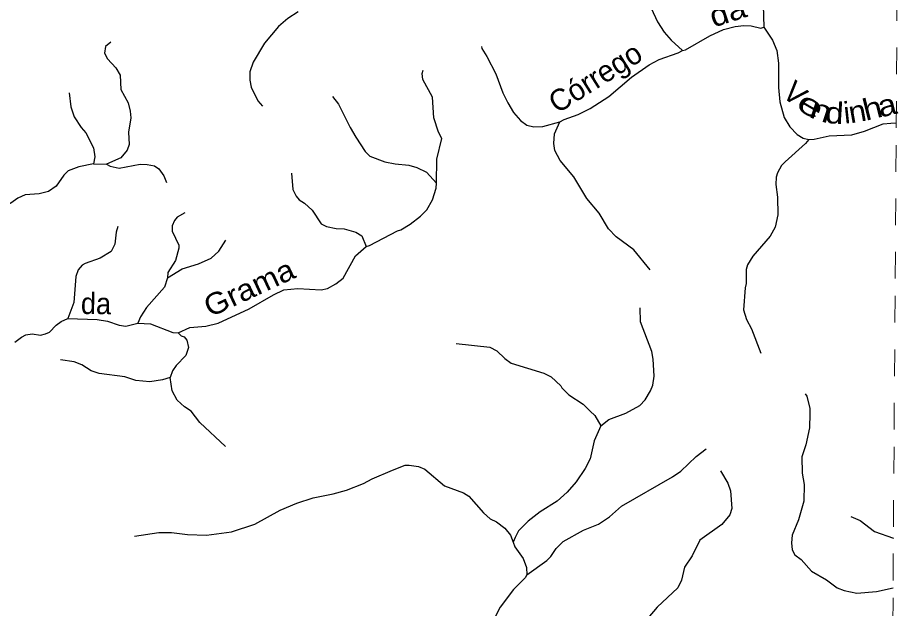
# Model space of a CAD drawing. Extents: x 577 to 602.9, y 7483.8 to 7511.6.
# Drawn here: x 599.47 to 602.787, y 7493.838 to 7496.049 of the extents above; entities that cross this region are included whole.
import ezdxf
from ezdxf.enums import TextEntityAlignment as Align

# ---------------------------------------------------------------- set-up
doc = ezdxf.new("R2010")
doc.units = 0
doc.header["$LTSCALE"] = 0.032
doc.linetypes.add('SHORT_DASHED', pattern=[2.7, 1.5, -1.2])
doc.layers.add('53', color=7, linetype='SHORT_DASHED', lineweight=13)
doc.layers.add('7', color=7, linetype='Continuous', lineweight=25)
doc.layers.add('61', color=7, linetype='Continuous')

msp = doc.modelspace()

# ---------------------------------------------------------------- linework, layer by layer
at = {"layer": '53'}
msp.add_lwpolyline([(602.7419, 7493.3777), (602.7457, 7493.9426), (602.7495, 7494.5074), (602.7533, 7495.0722), (602.7571, 7495.6371), (602.7609, 7496.2019), (602.7646, 7496.7668), (602.7684, 7497.3316), (602.7722, 7497.8964), (602.776, 7498.4613), (602.7798, 7499.0261), (602.7836, 7499.5909), (602.7874, 7500.1558)], dxfattribs=at)
at = {"layer": '7'}
for points in [[(601.7732, 7496.2353), (601.7792, 7496.1875), (601.8004, 7496.1368), (601.8405, 7496.0853), (601.8634, 7496.0338), (601.8887, 7495.9954), (601.9148, 7495.9652), (601.9574, 7495.9268)], [(602.3236, 7496.2227), (602.308, 7496.1949), (602.3015, 7496.1671), (602.2729, 7496.1295), (602.259, 7496.096), (602.2614, 7496.0134)], [(600.5195, 7496.0706), (600.4803, 7496.0461), (600.446, 7496.0159), (600.3937, 7495.9537), (600.3503, 7495.8826), (600.3389, 7495.8458), (600.3389, 7495.8148), (600.3438, 7495.7886), (600.3683, 7495.7379), (600.3851, 7495.718)], [(601.9574, 7495.9268), (601.9688, 7495.9284), (602.0595, 7495.9807), (602.111, 7496.0044), (602.1543, 7496.0159), (602.187, 7496.0199), (602.2148, 7496.0191), (602.25, 7496.0101), (602.2614, 7496.0134)], [(602.2614, 7496.0134), (602.2941, 7495.9652), (602.3105, 7495.9259), (602.3162, 7495.8785), (602.3162, 7495.7878), (602.3211, 7495.7339), (602.3383, 7495.6758), (602.3595, 7495.6399), (602.3865, 7495.6112), (602.4094, 7495.5982), (602.4298, 7495.5933)], [(599.8181, 7495.9579), (599.7978, 7495.9415), (599.7945, 7495.9161), (599.8051, 7495.8949), (599.837, 7495.8614), (599.8525, 7495.8336), (599.855, 7495.7804), (599.8828, 7495.7298), (599.8909, 7495.6987), (599.8926, 7495.6742), (599.8844, 7495.6202), (599.8869, 7495.5745), (599.8795, 7495.5532), (599.855, 7495.5246), (599.8019, 7495.5009)], [(601.2053, 7495.9411), (601.2062, 7495.9333), (601.2258, 7495.9039), (601.2593, 7495.8393), (601.2854, 7495.7674), (601.3034, 7495.7298), (601.3247, 7495.6946), (601.3517, 7495.6644), (601.3754, 7495.6472), (601.4007, 7495.6407), (601.435, 7495.6415), (601.498, 7495.6587)], [(601.498, 7495.6587), (601.5143, 7495.6685), (601.5674, 7495.6864), (601.6124, 7495.7093), (601.6819, 7495.7535), (601.7669, 7495.827), (601.8323, 7495.8728), (601.8699, 7495.8924), (601.9418, 7495.917), (601.9574, 7495.9268)], [(601.037, 7495.4298), (601.0386, 7495.5197), (601.0566, 7495.5965), (601.0443, 7495.6202), (601.0263, 7495.6742), (601.0222, 7495.751), (600.9855, 7495.818), (600.983, 7495.8401), (600.9864, 7495.8527)], [(599.6628, 7495.7677), (599.6686, 7495.7151), (599.6809, 7495.6783), (599.707, 7495.6382), (599.7242, 7495.6186), (599.7536, 7495.5614), (599.7585, 7495.5287), (599.7536, 7495.5017), (599.8019, 7495.5009)], [(600.6471, 7495.7539), (600.6699, 7495.7257), (600.7133, 7495.6374), (600.7353, 7495.6014), (600.7705, 7495.5483), (600.7868, 7495.5311), (600.844, 7495.5099), (600.8825, 7495.5017), (600.9331, 7495.4968), (600.9634, 7495.4886), (600.9994, 7495.4707), (601.037, 7495.4298)], [(601.8366, 7495.105), (601.7759, 7495.1797), (601.7089, 7495.2287), (601.6811, 7495.2581), (601.6451, 7495.3178), (601.5993, 7495.3726), (601.5503, 7495.4535), (601.4996, 7495.5148), (601.48, 7495.5524), (601.4759, 7495.5785), (601.4784, 7495.6145), (601.498, 7495.6587)], [(602.4298, 7495.5933), (602.4502, 7495.5941), (602.5066, 7495.6072), (602.5908, 7495.6104), (602.6383, 7495.6243), (602.7085, 7495.6513), (602.7372, 7495.6546), (602.7572, 7495.6551)], [(602.4298, 7495.5933), (602.4181, 7495.5777), (602.3415, 7495.5099), (602.3285, 7495.4952), (602.3129, 7495.4682), (602.308, 7495.4519), (602.3072, 7495.4249), (602.3129, 7495.3766), (602.3146, 7495.3113), (602.3039, 7495.2647), (602.2851, 7495.2312), (602.2206, 7495.1568), (602.2009, 7495.1233), (602.196, 7495.1069), (602.196, 7495.0538), (602.1919, 7495.0374), (602.1862, 7494.9549), (602.1969, 7494.9197), (602.2157, 7494.8846), (602.2505, 7494.7937)], [(599.7536, 7495.5017), (599.6989, 7495.4911), (599.6588, 7495.4756), (599.6416, 7495.4592), (599.613, 7495.4183), (599.5852, 7495.3979), (599.5501, 7495.3897), (599.4978, 7495.3856), (599.47, 7495.3734), (599.4438, 7495.3546), (599.4021, 7495.3358), (599.3711, 7495.3276), (599.3523, 7495.3268), (599.313, 7495.3292), (599.2493, 7495.3399), (599.1988, 7495.3381), (599.1968, 7495.338)], [(599.8019, 7495.5009), (599.8157, 7495.4927), (599.8493, 7495.4854), (599.9277, 7495.5009), (599.9547, 7495.5001), (599.9817, 7495.4944), (599.998, 7495.4837), (600.016, 7495.4568), (600.026, 7495.4323)], [(600.4943, 7495.4665), (600.4991, 7495.4053), (600.5122, 7495.3807), (600.5228, 7495.3677), (600.5432, 7495.3546), (600.571, 7495.3284), (600.6054, 7495.2769), (600.6258, 7495.2671), (600.6609, 7495.2598), (600.6912, 7495.2589), (600.7345, 7495.2467), (600.7574, 7495.232), (600.7737, 7495.1927)], [(600.7737, 7495.1927), (600.786, 7495.196), (600.8915, 7495.2516), (600.9037, 7495.2549), (600.9389, 7495.2761), (600.9773, 7495.3055), (601.001, 7495.3301), (601.0214, 7495.3668), (601.0353, 7495.411), (601.037, 7495.4298)], [(600.0956, 7495.319), (600.0667, 7495.3023), (600.0561, 7495.2892), (600.0479, 7495.2704), (600.0479, 7495.25), (600.0724, 7495.1976), (600.0724, 7495.1862), (600.0602, 7495.1396), (600.0315, 7495.0955), (600.0299, 7495.075)], [(599.8447, 7495.2674), (599.8378, 7495.2459), (599.8337, 7495.2009), (599.8198, 7495.1739), (599.7781, 7495.1486), (599.7217, 7495.129), (599.7103, 7495.1224), (599.6964, 7495.1053), (599.6874, 7495.0807), (599.6801, 7494.9827), (599.6572, 7494.923)], [(600.0299, 7495.075), (600.0855, 7495.1085), (600.1468, 7495.1273), (600.1934, 7495.1486), (600.222, 7495.1756), (600.2482, 7495.2164)], [(600.0697, 7494.8693), (600.1133, 7494.8895), (600.1738, 7494.8936), (600.2204, 7494.905), (600.3364, 7494.959), (600.4263, 7495.0113), (600.4656, 7495.0301), (600.5179, 7495.0358), (600.6054, 7495.0301), (600.6291, 7495.0358), (600.6601, 7495.0521), (600.6879, 7495.0742), (600.7337, 7495.1576), (600.7737, 7495.1927)], [(600.0299, 7495.075), (600.0185, 7495.0399), (599.9514, 7494.9647), (599.9294, 7494.9287), (599.9187, 7494.905)], [(601.6516, 7494.5208), (601.6819, 7494.5453), (601.7448, 7494.5682), (601.798, 7494.5977), (601.8176, 7494.6181), (601.838, 7494.6524), (601.8462, 7494.6737), (601.8519, 7494.7064), (601.8478, 7494.7701), (601.8421, 7494.7996), (601.8004, 7494.9107), (601.7985, 7494.9634)], [(599.4594, 7494.8339), (599.4839, 7494.8535), (599.5002, 7494.8617), (599.5239, 7494.8658), (599.555, 7494.8609), (599.573, 7494.865), (599.5885, 7494.8723), (599.613, 7494.8985), (599.6318, 7494.9115), (599.6572, 7494.923)], [(599.6572, 7494.923), (599.7675, 7494.9189), (599.8059, 7494.9132), (599.8493, 7494.8985), (599.8738, 7494.8944), (599.9187, 7494.905)], [(599.9187, 7494.905), (599.967, 7494.9026), (600.0503, 7494.8699), (600.0697, 7494.8693)], [(600.0697, 7494.8693), (600.0814, 7494.8576), (600.092, 7494.8543), (600.1027, 7494.8421), (600.1092, 7494.8143), (600.0986, 7494.784), (600.0626, 7494.7464), (600.0495, 7494.7268), (600.0397, 7494.7023)], [(601.111, 7494.8289), (601.2364, 7494.8159), (601.2626, 7494.802), (601.292, 7494.7726), (601.3157, 7494.7554), (601.4391, 7494.7186), (601.4661, 7494.7047), (601.5021, 7494.6712), (601.5061, 7494.6631), (601.5315, 7494.6377), (601.5854, 7494.6017), (601.6124, 7494.5764), (601.6296, 7494.5592), (601.6516, 7494.5208)], [(600.0397, 7494.7023), (600.012, 7494.6938), (599.9645, 7494.6859), (599.9114, 7494.6908), (599.8705, 7494.7047), (599.7741, 7494.717), (599.7446, 7494.7276), (599.7095, 7494.7489), (599.6809, 7494.7611), (599.6302, 7494.7686)], [(600.2468, 7494.4437), (600.1509, 7494.5339), (600.119, 7494.5764), (600.0937, 7494.5928), (600.0667, 7494.6173), (600.0479, 7494.6516), (600.0397, 7494.7023)], [(602.417, 7494.6407), (602.4233, 7494.632), (602.4339, 7494.5862), (602.4339, 7494.5674), (602.4331, 7494.5135), (602.4184, 7494.4497), (602.4037, 7494.4056), (602.4053, 7494.3434), (602.4126, 7494.3009), (602.411, 7494.2388), (602.3914, 7494.1693), (602.3677, 7494.1121), (602.3652, 7494.0835), (602.3677, 7494.0565), (602.3783, 7494.0377), (602.4012, 7494.0206), (602.4404, 7493.9772), (602.496, 7493.9446), (602.5369, 7493.9143), (602.5622, 7493.9045), (602.6105, 7493.8947), (602.6832, 7493.9012), (602.7455, 7493.9146)], [(601.6516, 7494.5208), (601.6271, 7494.4652), (601.6116, 7494.3974), (601.5936, 7494.3614), (601.5593, 7494.3108), (601.5258, 7494.2723), (601.4882, 7494.2396), (601.4244, 7494.1988), (601.3794, 7494.1644), (601.3443, 7494.1285), (601.3307, 7494.1026), (601.3232, 7494.0854)], [(601.3754, 7493.9634), (601.4497, 7494.0165), (601.4653, 7494.032), (601.4841, 7494.0614), (601.511, 7494.0876), (601.5871, 7494.1301), (601.6427, 7494.153), (601.6843, 7494.18), (601.7293, 7494.22), (601.9206, 7494.3296), (601.9508, 7494.3516), (602.008, 7494.4064), (602.0465, 7494.435)], [(599.9066, 7494.1081), (599.9972, 7494.1219), (600.0446, 7494.1219), (600.1051, 7494.1138), (600.1762, 7494.1121), (600.2694, 7494.1244), (600.3569, 7494.153), (600.4517, 7494.2053), (600.5146, 7494.2315), (600.5759, 7494.2519), (600.6503, 7494.2666), (600.7002, 7494.2805), (600.7639, 7494.305), (600.7958, 7494.323), (600.8718, 7494.3557), (600.9201, 7494.3737), (600.9348, 7494.3737), (600.9699, 7494.3688), (600.9928, 7494.359), (601.0664, 7494.296), (601.1375, 7494.2699), (601.1579, 7494.2576), (601.2127, 7494.1955), (601.2372, 7494.1734), (601.2617, 7494.1612), (601.2928, 7494.1375), (601.3132, 7494.1113), (601.3232, 7494.0854)], [(602.1002, 7494.3532), (602.1274, 7494.3067), (602.1372, 7494.2781), (602.1421, 7494.2118), (602.1347, 7494.1881), (602.1045, 7494.1514), (602.0227, 7494.0925), (601.9933, 7494.0345), (601.9647, 7493.992), (601.9541, 7493.9437), (601.9402, 7493.9151), (601.8625, 7493.8416), (601.7792, 7493.7435), (601.7285, 7493.6936)], [(602.5872, 7494.1816), (602.6227, 7494.1661), (602.6759, 7494.1252), (602.7468, 7494.1009)], [(601.3232, 7494.0854), (601.3296, 7494.068), (601.3606, 7494.0247), (601.3737, 7493.9911), (601.3754, 7493.9634)], [(601.3754, 7493.9634), (601.3688, 7493.9519), (601.3247, 7493.9078), (601.2756, 7493.8424), (601.2119, 7493.7173), (601.1939, 7493.6903), (601.1702, 7493.6642), (601.0615, 7493.5645), (601.0304, 7493.5187), (601.0075, 7493.4966), (600.9691, 7493.4476), (600.9397, 7493.3944), (600.9233, 7493.3478), (600.9078, 7493.2841), (600.8596, 7493.213), (600.84, 7493.177), (600.8359, 7493.1639), (600.8393, 7493.1168)]]:
    msp.add_lwpolyline(points, dxfattribs=at)

# ---------------------------------------------------------------- texts
at = {"layer": '61'}
for s, rotation, width, p in [('da', 17.895, 1.15, (602.1389, 7496.033)), ('e', 330.103, 1.6, (602.4183, 7495.6872)), ('n', 341.473, 1.35, (602.4646, 7495.6652)), ('d', 356.569, 1.15, (602.5239, 7495.6527)), ('h', 13.96, 1.2, (602.6776, 7495.6714)), ('a', 13.96, 1.15, (602.732, 7495.6831)), ('n', 10.136, 1.1, (602.6183, 7495.6591)), ('Grama', 24.963, 1.1, (600.3526, 7495.002)), ('da', 359.198, 0.95, (599.7621, 7494.9393))]:
    msp.add_text(s, height=0.08, rotation=rotation, dxfattribs=dict(at, width=width)).set_placement(p, align=Align.CENTER)
for s, rotation, p in [('Córrego', 32.283, (601.6522, 7495.7914)), ('V', 317.997, (602.3524, 7495.736)), ('i', 6.038, (602.5765, 7495.6537))]:
    msp.add_text(s, height=0.08, rotation=rotation, dxfattribs=at).set_placement(p, align=Align.CENTER)

doc.saveas('drawing.dxf')
